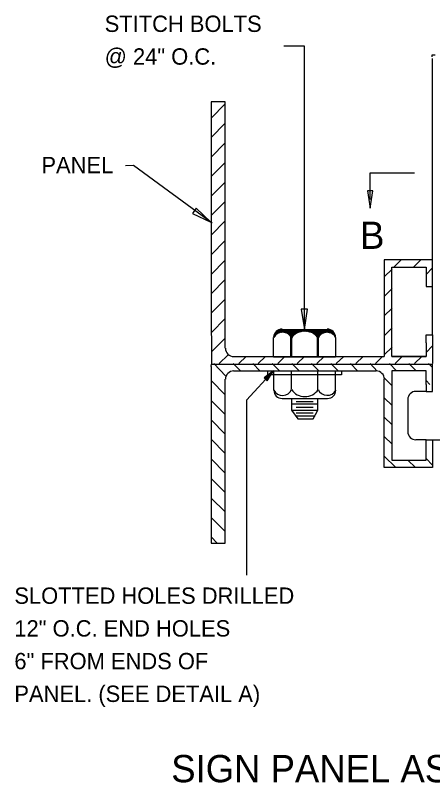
# Model space of a CAD drawing. Extents: x 150.3 to 157.3, y 91.3 to 101.4.
# Drawn here: x 150.351 to 151.88, y 98.396 to 101.211 of the extents above; entities that cross this region are included whole.
import ezdxf

# ---------------------------------------------------------------- set-up
doc = ezdxf.new("R2010")
doc.units = 0
for name, color, linetype in [('DETL-DIMS', 7, 'Continuous'), ('DETL-LINE', 7, 'Continuous'), ('DETL-NOTE', 7, 'Continuous'), ('DETL-PATT', 7, 'Continuous'), ('DETL-TITL', 7, 'Continuous')]:
    doc.layers.add(name, color=color, linetype=linetype)

msp = doc.modelspace()

# ---------------------------------------------------------------- linework, layer by layer
at = {"layer": 'DETL-DIMS'}
for p, q in [((151.4103, 101.0976), (151.3345, 101.0976)), ((151.4103, 100.0585), (151.4103, 101.0976)), ((151.6508, 100.5355), (151.6508, 100.633)), ((151.6508, 100.633), (151.8142, 100.633)), ((151.2975, 99.9063), (151.1986, 99.799)), ((151.1986, 99.799), (151.1986, 99.1568))]:
    msp.add_line(p, q, dxfattribs=at)
for points in [[(150.755, 100.6597), (150.7842, 100.6605), (151.0717, 100.4497)], [(151.2742, 99.8697), (151.2975, 99.9063), (151.2625, 99.8813), (151.2742, 99.8697)], [(151.2733, 99.8713), (151.2933, 99.9022), (151.2642, 99.8813), (151.2733, 99.8713)], [(151.2733, 99.873), (151.2892, 99.8988), (151.265, 99.8813), (151.2733, 99.873)], [(151.2733, 99.8747), (151.2858, 99.8947), (151.2675, 99.8813), (151.2733, 99.8747)], [(151.2733, 99.8763), (151.2817, 99.8905), (151.2683, 99.8813), (151.2733, 99.8763)], [(151.2733, 99.878), (151.2775, 99.8863), (151.2708, 99.8805), (151.2733, 99.878)], [(151.2725, 99.8797), (151.275, 99.8822), (151.2725, 99.8805), (151.2725, 99.8797)]]:
    msp.add_lwpolyline(points, dxfattribs=at)
for points in [[(151.6608, 100.5672), (151.6408, 100.5672), (151.6508, 100.5038)], [(151.0142, 100.5038), (151.0008, 100.4838), (151.0675, 100.4513)], [(151.4211, 100.1326), (151.3978, 100.1326), (151.4103, 100.0585)]]:
    msp.add_lwpolyline(points, close=True, dxfattribs=at)
at = {"layer": 'DETL-LINE'}
for p, q in [((151.8892, 101.0647), (151.8767, 101.0647)), ((151.8767, 101.0647), (151.8767, 101.058)), ((151.88, 100.038), (151.88, 101.0522)), ((151.0683, 100.8938), (151.0683, 100.1397)), ((151.12, 100.8938), (151.0683, 100.8938)), ((151.12, 99.9897), (151.12, 100.8938)), ((151.7025, 100.3138), (151.7025, 99.9588)), ((151.88, 100.3138), (151.7025, 100.3138)), ((151.88, 100.238), (151.88, 100.3138)), ((151.7308, 99.9588), (151.7308, 100.2863)), ((151.7308, 100.2863), (151.8558, 100.2863)), ((151.8558, 100.2863), (151.8558, 100.238)), ((151.8558, 100.238), (151.8558, 100.2163)), ((151.88, 100.2163), (151.88, 100.238)), ((151.8558, 100.2163), (151.88, 100.2163)), ((151.0683, 100.1397), (151.07, 99.9313)), ((151.297, 100.0326), (151.3236, 100.0585)), ((151.2978, 100.0343), (151.3211, 100.0585)), ((151.2986, 100.0376), (151.3195, 100.0585)), ((151.2995, 100.0401), (151.317, 100.0576)), ((151.3086, 100.0418), (151.3253, 100.0585)), ((151.3128, 100.0443), (151.3278, 100.0585)), ((151.3161, 100.046), (151.3295, 100.0585)), ((151.3195, 100.046), (151.332, 100.0585)), ((151.3211, 100.0476), (151.3336, 100.0585)), ((151.3236, 100.0476), (151.3353, 100.0585)), ((151.3253, 100.0476), (151.3361, 100.0585)), ((151.3278, 100.0585), (151.4928, 100.0585)), ((151.3278, 100.0485), (151.3378, 100.0585)), ((151.3295, 100.0485), (151.3403, 100.0585)), ((151.3311, 100.0485), (151.342, 100.0585)), ((151.3328, 100.0476), (151.3445, 100.0585)), ((151.3345, 100.0476), (151.3461, 100.0585)), ((151.3361, 100.0476), (151.347, 100.0585)), ((151.3378, 100.0468), (151.3495, 100.0585)), ((151.3386, 100.046), (151.3503, 100.0585)), ((151.3403, 100.046), (151.3528, 100.0585)), ((151.342, 100.046), (151.3545, 100.0585)), ((151.3428, 100.046), (151.357, 100.0585)), ((151.3445, 100.0451), (151.3586, 100.0585)), ((151.3453, 100.0443), (151.3595, 100.0585)), ((151.3461, 100.0435), (151.362, 100.0585)), ((151.3478, 100.0435), (151.3636, 100.0585)), ((151.3486, 100.0418), (151.3653, 100.0585)), ((151.3503, 100.0418), (151.3695, 100.0585)), ((151.3503, 100.0418), (151.367, 100.0585)), ((151.3511, 100.041), (151.3711, 100.0585)), ((151.3528, 100.0393), (151.372, 100.0585)), ((151.3536, 100.0385), (151.3745, 100.0585)), ((151.3545, 100.0376), (151.3761, 100.0585)), ((151.3553, 100.0368), (151.3778, 100.0585)), ((151.3561, 100.036), (151.3795, 100.0585)), ((151.357, 100.0343), (151.3811, 100.0585)), ((151.3578, 100.0335), (151.3836, 100.0585)), ((151.3586, 100.0326), (151.3845, 100.0585)), ((151.3595, 100.0301), (151.3886, 100.0585)), ((151.3595, 100.0318), (151.387, 100.0585)), ((151.3611, 100.0285), (151.392, 100.0585)), ((151.3611, 100.0293), (151.3903, 100.0585)), ((151.3753, 100.041), (151.3945, 100.0585)), ((151.3803, 100.0443), (151.3961, 100.0585)), ((151.3845, 100.046), (151.397, 100.0585)), ((151.3878, 100.0476), (151.3995, 100.0585)), ((151.3911, 100.0493), (151.4011, 100.0585)), ((151.3945, 100.0501), (151.4028, 100.0585)), ((151.3961, 100.0501), (151.4045, 100.0585)), ((151.3986, 100.051), (151.407, 100.0585)), ((151.4003, 100.0518), (151.4086, 100.0585)), ((151.4028, 100.0518), (151.4095, 100.0585)), ((151.4045, 100.0518), (151.412, 100.0585)), ((151.407, 100.0526), (151.4136, 100.0585)), ((151.4086, 100.0526), (151.4153, 100.0585)), ((151.4103, 100.0526), (151.417, 100.0585)), ((151.4128, 100.0526), (151.4195, 100.0585)), ((151.4136, 100.0526), (151.4211, 100.0585)), ((151.4153, 100.0526), (151.4228, 100.0585)), ((151.417, 100.0518), (151.4245, 100.0585)), ((151.4195, 100.0518), (151.4261, 100.0585)), ((151.4211, 100.0518), (151.4278, 100.0585)), ((151.422, 100.0518), (151.4295, 100.0585)), ((151.4236, 100.051), (151.432, 100.0585)), ((151.4253, 100.0501), (151.4336, 100.0585)), ((151.4261, 100.0501), (151.4353, 100.0585)), ((151.4278, 100.0501), (151.437, 100.0585)), ((151.4295, 100.0501), (151.4386, 100.0585)), ((151.4303, 100.0493), (151.4403, 100.0585)), ((151.432, 100.0493), (151.442, 100.0585)), ((151.4336, 100.0476), (151.4445, 100.0585)), ((151.4345, 100.0476), (151.4461, 100.0585)), ((151.4361, 100.0468), (151.447, 100.0585)), ((151.437, 100.046), (151.4495, 100.0585)), ((151.4378, 100.046), (151.4511, 100.0585)), ((151.4386, 100.0451), (151.4528, 100.0585)), ((151.4403, 100.0451), (151.4545, 100.0585)), ((151.4411, 100.0435), (151.457, 100.0585)), ((151.442, 100.0435), (151.4586, 100.0585)), ((151.4428, 100.0426), (151.4595, 100.0585)), ((151.4445, 100.0418), (151.462, 100.0585)), ((151.4461, 100.0418), (151.4636, 100.0585)), ((151.447, 100.041), (151.4653, 100.0585)), ((151.447, 100.0393), (151.467, 100.0585)), ((151.4486, 100.0385), (151.4695, 100.0585)), ((151.4503, 100.0376), (151.4711, 100.0585)), ((151.4503, 100.0376), (151.472, 100.0585)), ((151.4511, 100.0368), (151.4745, 100.0585)), ((151.4528, 100.0351), (151.4761, 100.0585)), ((151.4528, 100.0335), (151.4778, 100.0585)), ((151.4545, 100.0335), (151.4803, 100.0585)), ((151.4545, 100.0326), (151.482, 100.0585)), ((151.4553, 100.031), (151.4836, 100.0585)), ((151.457, 100.0301), (151.4845, 100.0585)), ((151.457, 100.0293), (151.487, 100.0585)), ((151.4586, 100.0293), (151.4886, 100.0585)), ((151.4745, 100.0426), (151.4903, 100.0585)), ((151.4778, 100.0451), (151.492, 100.0585)), ((151.4803, 100.046), (151.4945, 100.0585)), ((151.4836, 100.046), (151.4961, 100.0585)), ((151.4861, 100.0468), (151.497, 100.0585)), ((151.4878, 100.0476), (151.4986, 100.0585)), ((151.4903, 100.0476), (151.5003, 100.0585)), ((151.492, 100.0476), (151.5011, 100.0585)), ((151.4928, 100.0476), (151.5028, 100.0585)), ((151.4961, 100.0476), (151.5045, 100.0576)), ((151.497, 100.0476), (151.5053, 100.0568)), ((151.297, 100.0301), (151.3003, 100.0335)), ((151.297, 99.9585), (151.297, 100.0293)), ((151.297, 100.0293), (151.297, 100.0293)), ((151.3011, 100.0435), (151.3128, 100.056)), ((151.3053, 100.0493), (151.307, 100.051)), ((151.362, 100.0268), (151.3653, 100.0293)), ((151.4586, 100.0276), (151.4628, 100.0301)), ((151.4986, 100.0468), (151.507, 100.056)), ((151.5003, 100.0468), (151.5086, 100.0551)), ((151.5011, 100.046), (151.5095, 100.0543)), ((151.5028, 100.046), (151.5111, 100.0543)), ((151.5045, 100.046), (151.5111, 100.0535)), ((151.5053, 100.046), (151.5128, 100.0526)), ((151.507, 100.0451), (151.5136, 100.0518)), ((151.5086, 100.0443), (151.5136, 100.0501)), ((151.5095, 100.0435), (151.5153, 100.0501)), ((151.5111, 100.0435), (151.5161, 100.0493)), ((151.5111, 100.0418), (151.517, 100.0476)), ((151.5128, 100.0418), (151.5178, 100.0468)), ((151.5136, 100.0418), (151.5178, 100.046)), ((151.5136, 100.041), (151.5195, 100.0451)), ((151.5153, 100.0393), (151.5203, 100.0435)), ((151.517, 100.0385), (151.5211, 100.0426)), ((151.517, 100.0376), (151.5211, 100.0418)), ((151.5178, 100.0368), (151.522, 100.041)), ((151.5195, 100.036), (151.522, 100.0393)), ((151.5203, 100.0351), (151.522, 100.0376)), ((151.5211, 100.0335), (151.5236, 100.0368)), ((151.5211, 100.0335), (151.5236, 100.0343)), ((151.522, 100.0318), (151.5236, 100.0335)), ((151.5236, 100.0301), (151.5236, 100.0318)), ((151.5236, 100.0293), (151.5236, 99.9585)), ((151.5236, 100.0293), (151.5236, 100.0293)), ((151.8558, 100.0088), (151.8558, 100.038)), ((151.8558, 100.038), (151.88, 100.038)), ((151.88, 100.038), (151.88, 100.0263)), ((151.362, 100.026), (151.362, 99.9585)), ((151.4595, 100.0268), (151.4595, 100.0268)), ((151.4595, 100.026), (151.4595, 99.9585)), ((151.8558, 100.0088), (151.8558, 99.9588)), ((151.88, 100.0263), (151.88, 100.0097)), ((151.88, 100.0088), (151.88, 99.933)), ((151.1508, 99.9588), (151.7025, 99.9588)), ((151.297, 99.9585), (151.5236, 99.9585)), ((151.8558, 99.9588), (151.7308, 99.9588)), ((151.7308, 99.9588), (151.8558, 99.9588)), ((151.0683, 99.9222), (151.07, 99.9313)), ((151.0683, 99.9222), (151.0683, 99.2747)), ((151.07, 99.9313), (151.88, 99.9313)), ((151.88, 99.8563), (151.88, 99.9313)), ((151.1508, 99.9063), (151.6725, 99.9063)), ((151.2975, 99.9063), (151.2975, 99.8355)), ((151.3625, 99.8388), (151.3625, 99.9063)), ((151.46, 99.8388), (151.46, 99.9063)), ((151.5242, 99.8355), (151.5242, 99.9063)), ((151.8558, 99.9063), (151.7308, 99.9063)), ((151.7308, 99.9063), (151.7308, 99.5788)), ((151.8558, 99.8563), (151.8558, 99.9063)), ((151.12, 99.2747), (151.12, 99.8755)), ((151.7025, 99.5522), (151.7025, 99.8755)), ((151.8558, 99.8313), (151.819, 99.8313)), ((151.8558, 99.8563), (151.8558, 99.8313)), ((151.8558, 99.8313), (151.88, 99.8313)), ((151.88, 99.8313), (151.88, 99.8563)), ((151.3283, 99.8055), (151.4933, 99.8055)), ((151.3625, 99.8055), (151.3625, 99.7622)), ((151.46, 99.7622), (151.46, 99.8055)), ((151.3625, 99.7855), (151.46, 99.7855)), ((151.38, 99.7938), (151.4425, 99.7938)), ((151.789, 99.8013), (151.789, 99.6838)), ((151.3625, 99.7622), (151.46, 99.7622)), ((151.3625, 99.7622), (151.3867, 99.7305)), ((151.38, 99.773), (151.4425, 99.773)), ((151.38, 99.7522), (151.4425, 99.7522)), ((151.4425, 99.7305), (151.46, 99.7622)), ((151.3783, 99.7413), (151.4492, 99.7413)), ((151.3867, 99.7305), (151.4425, 99.7305)), ((151.8558, 99.6538), (151.819, 99.6538)), ((151.8558, 99.6272), (151.8558, 99.6538)), ((151.8558, 99.6538), (151.88, 99.6538)), ((151.88, 99.6538), (151.88, 99.623)), ((151.88, 99.6538), (152.0575, 99.6538)), ((151.8558, 99.5788), (151.8558, 99.6272)), ((151.88, 99.6272), (151.88, 99.5522)), ((151.7308, 99.5788), (151.8558, 99.5788)), ((151.88, 99.5522), (151.7025, 99.5522)), ((151.0683, 99.2747), (151.12, 99.2747))]:
    msp.add_line(p, q, dxfattribs=at)
for points in [[(151.3611, 99.9585), (151.3611, 100.0293), (151.3628, 100.0293), (151.3628, 99.9585)], [(151.4586, 99.9585), (151.4586, 100.0293), (151.4611, 100.0293), (151.4611, 99.9585)], [(151.2758, 99.9063), (151.5458, 99.9063), (151.5458, 99.8922), (151.2758, 99.8922)]]:
    msp.add_lwpolyline(points, close=True, dxfattribs=at)
for centre, radius, start, end in [((151.3283, 100.029), 0.0304, 90, 180), ((151.4942, 100.029), 0.0304, 0, 90), ((151.3297, 100.0129), 0.0356, 22.2447, 153.0541), ((151.4115, 99.9942), 0.0585, 33.3007, 146.6993), ((151.4931, 100.0125), 0.0355, 27.6057, 157.126), ((151.1514, 99.9891), 0.0304, 180, 270), ((151.1514, 99.8757), 0.0304, 90, 180), ((151.673, 99.8757), 0.0304, 0, 90), ((151.3302, 99.8518), 0.0356, 206.9459, 337.7553), ((151.3288, 99.8357), 0.0304, 180, 270), ((151.412, 99.8705), 0.0585, 213.3007, 326.6993), ((151.4936, 99.8522), 0.0355, 202.874, 332.3943), ((151.4947, 99.8357), 0.0304, 270, 0), ((151.819, 99.8013), 0.03, 90, 180), ((151.819, 99.6838), 0.03, 180, 270)]:
    msp.add_arc(centre, radius, start, end, dxfattribs=at)
at = {"layer": 'DETL-PATT'}
for p, q in [((151.0683, 100.833), (151.12, 100.8855)), ((151.0683, 100.7622), (151.12, 100.8147)), ((151.0683, 100.6905), (151.12, 100.743)), ((151.0683, 100.6188), (151.12, 100.6705)), ((151.0683, 100.5472), (151.12, 100.5988)), ((151.0683, 100.4763), (151.12, 100.5272)), ((151.0683, 100.4047), (151.12, 100.4563)), ((151.0683, 100.3322), (151.12, 100.3847)), ((151.0683, 100.2605), (151.12, 100.313)), ((151.7383, 100.2863), (151.765, 100.3138)), ((151.81, 100.2863), (151.8367, 100.3138)), ((151.8558, 100.2605), (151.88, 100.2847)), ((151.7025, 100.2513), (151.7317, 100.2797)), ((151.0683, 100.1888), (151.12, 100.2413)), ((151.7025, 100.1788), (151.7317, 100.208)), ((151.0683, 100.118), (151.12, 100.1697)), ((151.7025, 100.108), (151.7317, 100.1363)), ((151.07, 100.0472), (151.12, 100.098)), ((151.7025, 100.0355), (151.7317, 100.0647)), ((151.07, 99.9763), (151.12, 100.0263)), ((151.7025, 99.9647), (151.7317, 99.9938)), ((151.8558, 99.9738), (151.88, 99.998)), ((151.0975, 99.933), (151.1308, 99.9655)), ((151.17, 99.933), (151.1967, 99.9588)), ((151.2408, 99.933), (151.2675, 99.9588)), ((151.3125, 99.933), (151.3383, 99.9588)), ((151.3842, 99.933), (151.41, 99.9588)), ((151.4558, 99.933), (151.4825, 99.9588)), ((151.5267, 99.933), (151.5542, 99.9588)), ((151.5992, 99.933), (151.6258, 99.9588)), ((151.6708, 99.933), (151.6967, 99.9588)), ((151.7425, 99.933), (151.7683, 99.9588)), ((151.8142, 99.933), (151.84, 99.9588)), ((151.1225, 99.8872), (151.0783, 99.933)), ((151.1758, 99.9063), (151.1492, 99.933)), ((151.2475, 99.9063), (151.2217, 99.933)), ((151.3192, 99.9063), (151.2925, 99.933)), ((151.3908, 99.9063), (151.3642, 99.933)), ((151.4625, 99.9063), (151.4367, 99.933)), ((151.5342, 99.9063), (151.5075, 99.933)), ((151.605, 99.9063), (151.5792, 99.933)), ((151.6767, 99.9055), (151.6508, 99.933)), ((151.7475, 99.9063), (151.7225, 99.933)), ((151.82, 99.9063), (151.7933, 99.933)), ((151.88, 99.9188), (151.865, 99.933)), ((151.12, 99.8188), (151.0683, 99.8705)), ((151.7317, 99.8513), (151.7025, 99.8805)), ((151.87, 99.8563), (151.8558, 99.8705)), ((151.7317, 99.7797), (151.7025, 99.808)), ((151.12, 99.7463), (151.0683, 99.798)), ((151.12, 99.6747), (151.0683, 99.7272)), ((151.7317, 99.708), (151.7025, 99.7372)), ((151.7317, 99.6372), (151.7025, 99.6655)), ((151.12, 99.6038), (151.0683, 99.6555)), ((151.12, 99.5313), (151.0683, 99.5838)), ((151.745, 99.5522), (151.7025, 99.5938)), ((151.8175, 99.5522), (151.7892, 99.5788)), ((151.88, 99.5605), (151.8558, 99.5847)), ((151.12, 99.4605), (151.0683, 99.5122)), ((151.12, 99.3888), (151.0683, 99.4397)), ((151.12, 99.3172), (151.0683, 99.3688)), ((151.0908, 99.2747), (151.0683, 99.2972))]:
    msp.add_line(p, q, dxfattribs=at)

# ---------------------------------------------------------------- texts
at = {"layer": 'DETL-NOTE'}
for s, height, p in [('STITCH BOLTS', 0.06, (150.6785, 101.1496)), ('@ 24" O.C.', 0.06, (150.6785, 101.0296)), ('PANEL', 0.06, (150.4467, 100.6313)), ('B', 0.1, (151.6142, 100.3538)), ('SLOTTED HOLES DRILLED ', 0.06, (150.3476, 99.0519)), ('12" O.C. END HOLES', 0.06, (150.3476, 98.9319)), ('6" FROM ENDS OF ', 0.06, (150.3476, 98.8119)), ('PANEL. (SEE DETAIL A)', 0.06, (150.3476, 98.6919))]:
    msp.add_text(s, height=height, dxfattribs=at).set_placement(p)
at = {"layer": 'DETL-TITL'}
msp.add_text('SIGN PANEL ASSEMBLY', height=0.1, dxfattribs=at).set_placement((150.9223, 98.3974))

doc.saveas('drawing.dxf')
